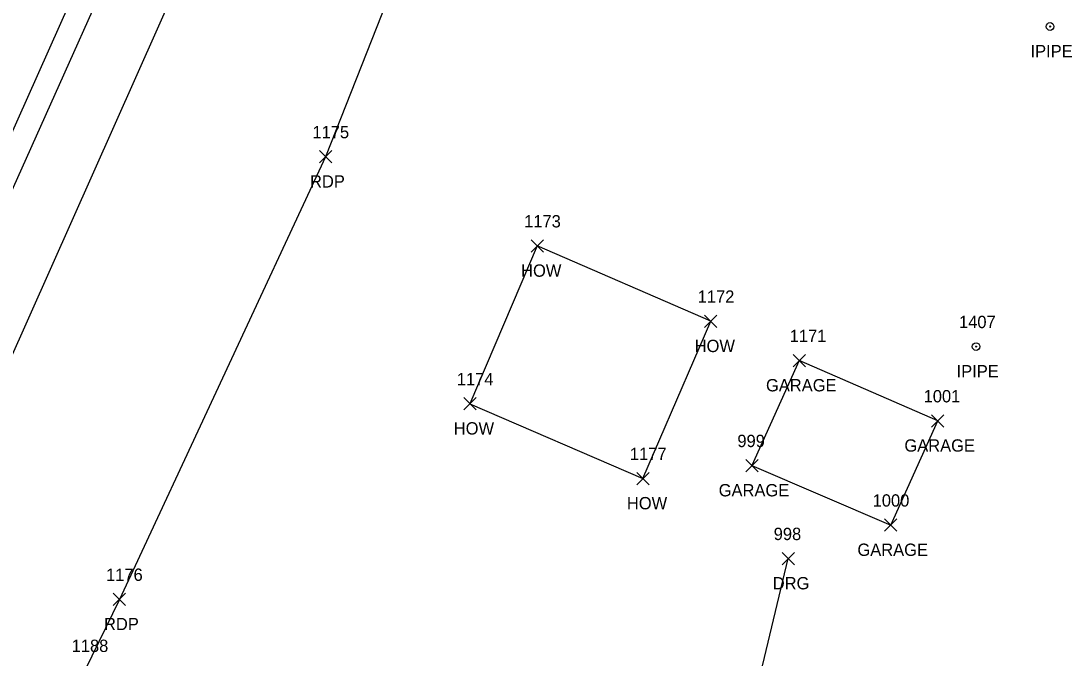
# Model space of a CAD drawing. Extents: x 1767353 to 1772625, y 740790 to 747702.
# Drawn here: x 1770077.3 to 1770245.8, y 742566 to 742669.5 of the extents above; entities that cross this region are included whole.
import ezdxf

# ---------------------------------------------------------------- set-up
doc = ezdxf.new("R2010")
doc.units = 0
for name, color, linetype in [('L_A', 7, 'Continuous'), ('L_I', 7, 'Continuous'), ('L_TIC', 7, 'Continuous'), ('LBC', 7, 'Continuous'), ('M_A', 7, 'Continuous'), ('M_I', 7, 'Continuous'), ('MPIP', 7, 'Continuous'), ('P_A', 7, 'Continuous'), ('P_I', 7, 'Continuous'), ('P_TIC', 7, 'Continuous'), ('PET', 7, 'Continuous'), ('R_A', 7, 'Continuous'), ('R_I', 7, 'Continuous'), ('R_TIC', 7, 'Continuous'), ('RDG', 7, 'Continuous'), ('RSW', 7, 'Continuous')]:
    doc.layers.add(name, color=color, linetype=linetype)

msp = doc.modelspace()

# ---------------------------------------------------------------- linework, layer by layer
at = {"layer": 'L_TIC'}
for points in [[(1770160.11, 742631.96), (1770162.11, 742633.96)], [(1770162.11, 742631.96), (1770160.11, 742633.96)], [(1770188.27, 742619.73), (1770190.27, 742621.73)], [(1770190.27, 742619.73), (1770188.27, 742621.73)], [(1770202.62, 742613.35), (1770204.62, 742615.35)], [(1770204.62, 742613.35), (1770202.62, 742615.35)], [(1770149.19, 742606.35), (1770151.19, 742608.35)], [(1770151.19, 742606.35), (1770149.19, 742608.35)], [(1770225.07, 742603.57), (1770227.07, 742605.57)], [(1770227.07, 742603.57), (1770225.07, 742605.57)], [(1770194.95, 742596.31), (1770196.95, 742598.31)], [(1770196.95, 742596.31), (1770194.95, 742598.31)], [(1770177.27, 742594.21), (1770179.27, 742596.21)], [(1770179.27, 742594.21), (1770177.27, 742596.21)], [(1770217.45, 742586.65), (1770219.45, 742588.65)], [(1770219.45, 742586.65), (1770217.45, 742588.65)]]:
    msp.add_lwpolyline(points, dxfattribs=at)
at = {"layer": 'LBC'}
for points in [[(1770189.27, 742620.73), (1770161.11, 742632.96), (1770150.19, 742607.35), (1770178.27, 742595.21)], [(1770178.27, 742595.21), (1770189.27, 742620.73)], [(1770203.62, 742614.35), (1770195.95, 742597.31)], [(1770226.07, 742604.57), (1770203.62, 742614.35)], [(1770195.95, 742597.31), (1770218.45, 742587.65), (1770226.07, 742604.57)]]:
    msp.add_lwpolyline(points, dxfattribs=at)
at = {"layer": 'MPIP'}
for centre, radius in [((1770244.3, 742668.57), 0.625), ((1770244.3, 742668.57), 0.0833), ((1770232.3, 742616.62), 0.625), ((1770232.3, 742616.62), 0.0833)]:
    msp.add_circle(centre, radius, dxfattribs=at)
at = {"layer": 'P_TIC'}
for points in [[(1770125.77, 742646.43), (1770127.77, 742648.43)], [(1770127.77, 742646.43), (1770125.77, 742648.43)], [(1770092.35, 742574.6), (1770094.35, 742576.6)], [(1770094.35, 742574.6), (1770092.35, 742576.6)]]:
    msp.add_lwpolyline(points, dxfattribs=at)
at = {"layer": 'PET'}
for points in [[(1770287.36, 743218.01), (1770265.05, 743131.43), (1770236.51, 743031.56), (1770219.34, 742972.95), (1770201.78, 742917.74), (1770184.32, 742871.03), (1770170.89, 742832.33), (1770155.31, 742796.84), (1770127.15, 742730.43), (1770071.7, 742605.94), (1770068.18, 742600.07), (1770059.84, 742596.32), (1770058.18, 742592.27), (1770056.9, 742590.58), (1770055.34, 742589.72), (1770052.72, 742590.21), (1770049.12, 742591.83), (1770036.26, 742597.45)], [(1770147.48, 742699.94), (1770126.77, 742647.43), (1770093.35, 742575.6), (1770087.72, 742564.06), (1770014.02, 742398.02), (1769942.32, 742243.2), (1769914.15, 742124.85), (1769908.32, 742119.68), (1769902.88, 742101.36), (1769903.35, 742099.19), (1769904.66, 742097.46), (1769909.68, 742095.79), (1770083.39, 742045.68), (1770106.4, 742043.42), (1770086.96, 742009.25), (1770086.23, 742007.27), (1770086.55, 742005.47), (1770087.9, 742003.62), (1770089.26, 742002.56), (1770097.29, 741998.16), (1770140.08, 741981.73)]]:
    msp.add_lwpolyline(points, dxfattribs=at)
at = {"layer": 'R_TIC'}
for points in [[(1770200.83, 742581.22), (1770202.83, 742583.22)], [(1770202.83, 742581.22), (1770200.83, 742583.22)]]:
    msp.add_lwpolyline(points, dxfattribs=at)
at = {"layer": 'RDG'}
msp.add_lwpolyline([(1770204.13, 742500.37), (1770216.45, 742489.14), (1770211.23, 742464.55), (1770235.77, 742456.2), (1770257.57, 742458.3), (1770267.19, 742526.02), (1770193.8, 742548.72), (1770201.83, 742582.22)], dxfattribs=at)
at = {"layer": 'RSW'}
for points in [[(1770224.69, 743035.2), (1770205.97, 742977.24), (1770187.9, 742922.34), (1770172.36, 742876.56), (1770157.95, 742836.89), (1770142.69, 742800.86), (1770114.37, 742737.77), (1770052.67, 742599.45), (1770040.21, 742604.87)], [(1770228.29, 743034.19), (1770209.52, 742976.05), (1770191.6, 742920.92), (1770175.94, 742874.88), (1770161.68, 742835.7), (1770145.6, 742799.3), (1770117.99, 742736.11), (1770056.07, 742597.76), (1770059.84, 742596.32)]]:
    msp.add_lwpolyline(points, dxfattribs=at)

# ---------------------------------------------------------------- texts
at = {"layer": 'L_A'}
for s, p in [('HOW', (1770158.5, 742627.96)), ('HOW', (1770186.65, 742615.73)), ('GARAGE', (1770198.22, 742609.35)), ('HOW', (1770147.58, 742602.35)), ('GARAGE', (1770220.67, 742599.57)), ('GARAGE', (1770190.55, 742592.31)), ('HOW', (1770175.66, 742590.21)), ('GARAGE', (1770213.05, 742582.65))]:
    msp.add_text(s, height=2, dxfattribs=at).set_placement(p)
at = {"layer": 'L_I'}
for s, p in [('1173', (1770158.99, 742635.96)), ('1172', (1770187.14, 742623.73)), ('1171', (1770202.06, 742617.35)), ('1174', (1770148.07, 742610.35)), ('1001', (1770223.79, 742607.57)), ('999', (1770193.58, 742600.31)), ('1177', (1770176.14, 742598.21)), ('1000', (1770215.52, 742590.65))]:
    msp.add_text(s, height=2, dxfattribs=at).set_placement(p)
at = {"layer": 'M_A'}
for p in [(1770241.13, 742663.57), (1770229.14, 742611.62)]:
    msp.add_text('IPIPE', height=2, dxfattribs=at).set_placement(p)
at = {"layer": 'M_I'}
msp.add_text('1407', height=2, dxfattribs=at).set_placement((1770229.53, 742619.62))
at = {"layer": 'P_A'}
for p in [(1770124.26, 742642.43), (1770090.84, 742570.6)]:
    msp.add_text('RDP', height=2, dxfattribs=at).set_placement(p)
at = {"layer": 'P_I'}
for s, p in [('1175', (1770124.65, 742650.43)), ('1176', (1770091.17, 742578.6)), ('1188', (1770085.59, 742567.06))]:
    msp.add_text(s, height=2, dxfattribs=at).set_placement(p)
at = {"layer": 'R_A'}
msp.add_text('DRG', height=2, dxfattribs=at).set_placement((1770199.32, 742577.22))
at = {"layer": 'R_I'}
msp.add_text('998', height=2, dxfattribs=at).set_placement((1770199.47, 742585.22))

doc.saveas('drawing.dxf')
